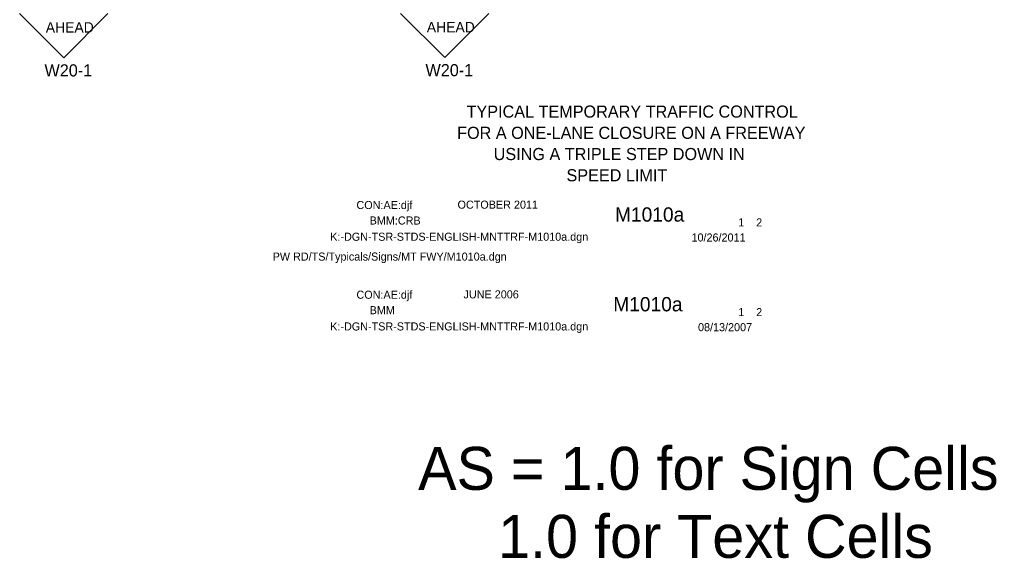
# Model space of a CAD drawing. Extents: x 16734 to 18479, y 5690 to 6925.
# Drawn here: x 16832 to 17582, y 5690 to 6104 of the extents above; entities that cross this region are included whole.
import ezdxf

# ---------------------------------------------------------------- set-up
doc = ezdxf.new("R2010")
doc.units = 0
for name, color, linetype in [('BORDER', 7, 'Continuous'), ('BORDER_SIGNAL_WO', 7, 'Continuous'), ('TRAFFIC_SIGNS_PR', 7, 'Continuous')]:
    doc.layers.add(name, color=color, linetype=linetype)

msp = doc.modelspace()

# ---------------------------------------------------------------- linework, layer by layer
at = {"layer": 'TRAFFIC_SIGNS_PR'}
for p, q in [((16832.01, 6108.15), (16865.95, 6074.21)), ((16865.95, 6074.21), (16899.9, 6108.15)), ((17124.54, 6108.34), (17158.48, 6074.4)), ((17158.48, 6074.4), (17192.42, 6108.34))]:
    msp.add_line(p, q, dxfattribs=at)

# ---------------------------------------------------------------- texts
at = {"layer": 'BORDER'}
for s, p in [('TYPICAL TEMPORARY TRAFFIC CONTROL', (17175.21, 6028.27)), ('FOR A ONE-LANE CLOSURE ON A FREEWAY', (17167.99, 6011.97)), ('USING A TRIPLE STEP DOWN IN', (17196.04, 5995.67)), ('SPEED LIMIT', (17251.92, 5979.37))]:
    msp.add_text(s, height=9.3, dxfattribs=at).set_placement(p)
at = {"layer": 'BORDER_SIGNAL_WO'}
for s, height, p in [('CON:AE:djf  ', 6.2, (17090.69, 5958.06)), ('    OCTOBER 2011    ', 6.2, (17159.08, 5958.34)), ('    M1010a   ', 11, (17272.86, 5948.38)), ('BMM:CRB   ', 6.2, (17100.81, 5946.17)), (' 1    2 ', 6.2, (17381.45, 5944.7)), ('K:-DGN-TSR-STDS-ENGLISH-MNTTRF-M1010a.dgn      ', 6.2, (17070.55, 5933.71)), ('10/26/2011    ', 6.2, (17347.93, 5933.13)), ('PW RD/TS/Typicals/Signs/MT FWY/M1010a.dgn      ', 6.2, (17026.36, 5918.46)), ('CON:AE:djf', 6.2, (17090.69, 5889.17)), ('      JUNE 2006     ', 6.2, (17159.08, 5889.45)), ('    M1010a   ', 11, (17271.53, 5879.49)), ('BMM       ', 6.2, (17100.81, 5877.29)), (' 1    2 ', 6.2, (17381.45, 5875.81)), ('K:-DGN-TSR-STDS-ENGLISH-MNTTRF-M1010a.dgn         ', 6.2, (17070.55, 5864.82)), ('08/13/2007', 6.2, (17352.93, 5864.24)), ('AS = 1.0 for Sign Cells', 33.0301, (17138.06, 5742.42)), ('     1.0 for Text Cells', 33.0301, (17138.06, 5690.19))]:
    msp.add_text(s, height=height, dxfattribs=at).set_placement(p)
at = {"layer": 'TRAFFIC_SIGNS_PR'}
for s, height, p in [('AHEAD', 8, (16852.16, 6093.57)), ('AHEAD', 8, (17144.68, 6093.76)), ('W20-1', 9.3, (16851.17, 6059.91)), ('W20-1', 9.3, (17143.69, 6060.1))]:
    msp.add_text(s, height=height, dxfattribs=at).set_placement(p)

doc.saveas('drawing.dxf')
